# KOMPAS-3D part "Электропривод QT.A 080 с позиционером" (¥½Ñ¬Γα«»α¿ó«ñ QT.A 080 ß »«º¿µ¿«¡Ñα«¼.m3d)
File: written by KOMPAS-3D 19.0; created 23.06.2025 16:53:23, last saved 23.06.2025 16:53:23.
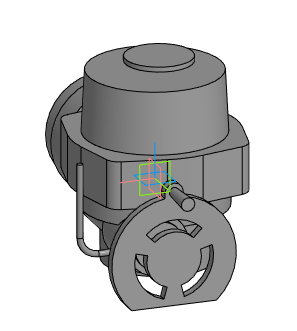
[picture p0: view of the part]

Document properties: Автор: Евгений; Полное имя файла: E:\Dendor Работа Сачек\3D для проектировщиков\3.5 Тип QT.А Электропривод\stp_Электропривод QT.A с позиционером\Электропривод QT.A 080 с позиционером.m3d

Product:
- Part/product: Электропривод QT.A 080 с позиционером

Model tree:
1. Операция без истории:1  (labels: Электропривод QT.A 080 с позиционером)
